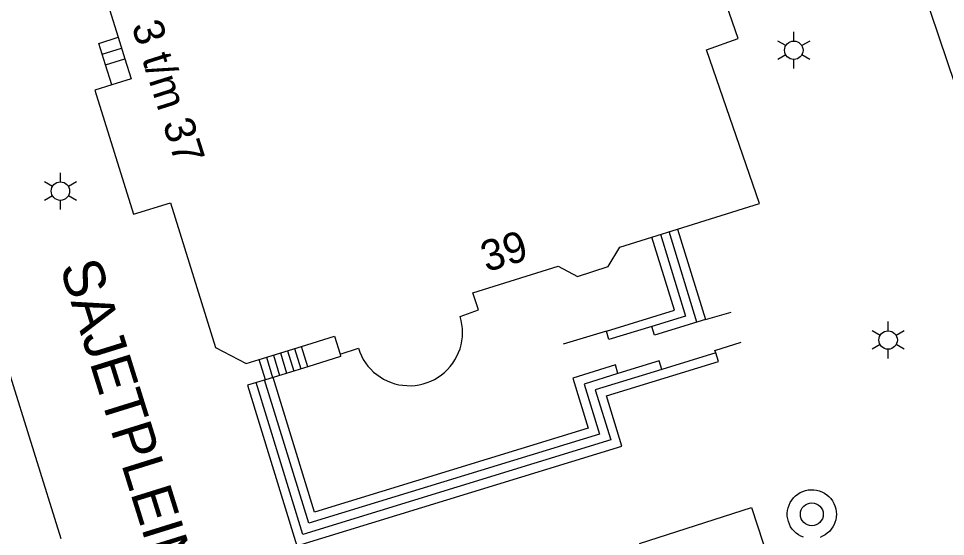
# Model space of a CAD drawing. Extents: x 122462 to 123306, y 485548 to 486417.
# Drawn here: x 122737.17 to 122782.47, y 485976.7 to 486002.03 of the extents above; entities that cross this region are included whole.
import ezdxf

# ---------------------------------------------------------------- set-up
doc = ezdxf.new("R2010")
doc.units = 0
for name, color, linetype in [('B-WE-IE-MEUBILAIR_WEGMEUBILAIR_VERKEERSBORD-S', 7, 'Continuous'), ('Level 1', 7, 'Continuous'), ('Level 17', 7, 'Continuous'), ('Level 22', 7, 'Continuous'), ('Level 30', 7, 'Continuous'), ('Level 31', 7, 'Continuous'), ('Level 33', 7, 'Continuous'), ('Level 50', 7, 'Continuous'), ('Level 53', 7, 'Continuous'), ('N-WE-GR-BOOM_DOORWORTELBARE RUIMTE-G', 7, 'Continuous')]:
    doc.layers.add(name, color=color, linetype=linetype)

msp = doc.modelspace()

# ---------------------------------------------------------------- linework, layer by layer
at = {"layer": 'Level 1'}
for p, q in [((122742.047, 486001.11), (122742.374, 486000.064)), ((122768.123, 485991.344), (122769.382, 485991.735)), ((122748.937, 485985.362), (122751.002, 485985.998))]:
    msp.add_line(p, q, dxfattribs=at)
for points in [[(122769.382, 485991.735), (122773.379, 485992.979), (122770.801, 486000.495), (122772.347, 486001.049), (122768.48, 486012.214), (122766.934, 486011.66), (122765.489, 486015.809), (122762.16, 486015.37), (122762.111, 486015.511), (122758.815, 486014.935)], [(122787.249, 485986.219), (122784.617, 485994.164), (122784.519, 485994.13), (122781.37, 486003.489), (122781.464, 486003.523), (122780.204, 486007.34), (122779.88, 486007.229), (122778.84, 486010.312)], [(122741.239, 486007.623), (122740.478, 486006.134), (122742.047, 486001.11)], [(122742.374, 486000.064), (122742.678, 485999.087), (122741.727, 485998.784)], [(122741.727, 485998.784), (122740.902, 485998.519), (122742.798, 485992.458), (122744.591, 485993.01), (122746.797, 485985.94), (122748.292, 485985.163), (122748.937, 485985.362)], [(122752.882, 485985.619), (122753.781, 485985.909), (122753.847, 485985.721), (122753.928, 485985.538), (122754.022, 485985.362), (122754.13, 485985.194), (122754.25, 485985.034), (122754.382, 485984.884), (122754.525, 485984.745), (122754.678, 485984.617), (122754.84, 485984.501), (122755.011, 485984.398), (122755.19, 485984.309), (122755.375, 485984.233), (122755.565, 485984.172), (122755.759, 485984.125), (122755.956, 485984.094), (122756.155, 485984.077), (122756.355, 485984.076), (122756.554, 485984.091), (122756.751, 485984.12), (122756.946, 485984.165), (122757.137, 485984.224), (122757.322, 485984.298), (122757.501, 485984.385), (122757.674, 485984.487), (122757.837, 485984.601), (122757.992, 485984.727), (122758.136, 485984.865), (122758.27, 485985.013), (122758.392, 485985.172), (122758.501, 485985.339), (122758.597, 485985.514), (122758.679, 485985.696), (122758.747, 485985.883), (122758.801, 485986.076), (122758.84, 485986.271), (122758.863, 485986.47), (122758.872, 485986.669), (122758.865, 485986.869), (122758.843, 485987.067), (122758.805, 485987.263), (122758.753, 485987.456), (122759.656, 485987.782), (122759.373, 485988.621), (122763.536, 485989.916), (122764.489, 485989.41), (122765.991, 485989.903), (122766.559, 485990.857), (122768.123, 485991.344)], [(122733.475, 485990.149), (122733.73, 485990.221), (122733.739, 485990.192), (122734.831, 485990.479), (122735.166, 485989.288), (122735.272, 485989.314), (122739.244, 485976.609)], [(122751.002, 485985.998), (122752.614, 485986.495), (122752.882, 485985.619)]]:
    msp.add_lwpolyline(points, dxfattribs=at)
at = {"layer": 'Level 17'}
msp.add_lwpolyline([(122775.529, 485976.661), (122775.402, 485976.716), (122775.283, 485976.785), (122775.172, 485976.866), (122775.072, 485976.96), (122774.982, 485977.065), (122774.906, 485977.18), (122774.843, 485977.302), (122774.794, 485977.431), (122774.761, 485977.565), (122774.743, 485977.701), (122774.74, 485977.839), (122774.754, 485977.976), (122774.783, 485978.111), (122774.828, 485978.241), (122774.887, 485978.366), (122774.96, 485978.482), (122775.046, 485978.59), (122775.143, 485978.687), (122775.252, 485978.773), (122775.369, 485978.845), (122775.494, 485978.903), (122775.624, 485978.947), (122775.759, 485978.976), (122775.896, 485978.989), (122776.034, 485978.986), (122776.17, 485978.967), (122776.304, 485978.933), (122776.432, 485978.884), (122776.555, 485978.82), (122776.669, 485978.743), (122776.773, 485978.653), (122776.867, 485978.552), (122776.948, 485978.44), (122777.016, 485978.321), (122777.07, 485978.194), (122777.108, 485978.062), (122777.132, 485977.926), (122777.14, 485977.788), (122777.132, 485977.651), (122777.108, 485977.515), (122777.069, 485977.383), (122777.032, 485977.292), (122776.968, 485977.17), (122776.89, 485977.056), (122776.8, 485976.952), (122776.698, 485976.859), (122776.587, 485976.778), (122776.467, 485976.711), (122776.34, 485976.658)], dxfattribs=at)
at = {"layer": 'Level 22'}
msp.add_lwpolyline([(122767.513, 485976.36), (122772.987, 485978.112), (122773.834, 485975.529)], dxfattribs=at)
at = {"layer": 'Level 30'}
for p, q in [((122741.42, 485999.766), (122742.374, 486000.064)), ((122741.727, 485998.784), (122741.42, 485999.766)), ((122751.308, 485985.002), (122751.002, 485985.998))]:
    msp.add_line(p, q, dxfattribs=at)
msp.add_lwpolyline([(122752.882, 485985.619), (122752.913, 485985.496), (122751.308, 485985.002)], dxfattribs=at)
at = {"layer": 'Level 31'}
for p, q in [((122749.242, 485984.368), (122748.937, 485985.362)), ((122751.308, 485985.002), (122749.619, 485984.484)), ((122749.619, 485984.484), (122749.242, 485984.368))]:
    msp.add_line(p, q, dxfattribs=at)
for points in [[(122741.42, 485999.766), (122741.093, 486000.812), (122742.047, 486001.11)], [(122769.382, 485991.735), (122770.741, 485987.313), (122768.256, 485986.551), (122768.127, 485986.972), (122766.027, 485986.327), (122765.898, 485986.747), (122769.221, 485987.768), (122768.123, 485991.344)], [(122749.242, 485984.368), (122748.357, 485984.095), (122750.77, 485976.243), (122766.661, 485981.126), (122765.908, 485983.575), (122771.373, 485985.255), (122771.244, 485985.676), (122768.61, 485984.866), (122768.48, 485985.287), (122766.467, 485984.668), (122766.338, 485985.088), (122764.259, 485984.449), (122765.011, 485982.004), (122751.643, 485977.896), (122749.619, 485984.484)]]:
    msp.add_lwpolyline(points, dxfattribs=at)
at = {"layer": 'Level 33'}
for p, q in [((122741.256, 486000.289), (122742.21, 486000.587)), ((122770.322, 485987.185), (122768.961, 485991.614)), ((122770.741, 485987.313), (122772, 485987.67)), ((122765.898, 485986.747), (122763.79, 485986.1)), ((122750.658, 485985.892), (122750.963, 485984.897)), ((122749.282, 485985.468), (122749.587, 485984.474)), ((122749.626, 485985.574), (122749.931, 485984.58)), ((122749.97, 485985.68), (122750.275, 485984.685)), ((122750.314, 485985.786), (122750.619, 485984.791))]:
    msp.add_line(p, q, dxfattribs=at)
for points in [[(122768.541, 485991.484), (122769.771, 485987.477), (122768.127, 485986.972)], [(122771.244, 485985.676), (122771.205, 485985.803), (122772.489, 485986.198)], [(122768.61, 485984.866), (122765.36, 485983.867), (122766.112, 485981.422), (122751.061, 485976.797), (122748.778, 485984.225)], [(122766.467, 485984.668), (122764.809, 485984.158), (122765.561, 485981.713), (122751.352, 485977.347), (122749.199, 485984.355)]]:
    msp.add_lwpolyline(points, dxfattribs=at)
at = {"layer": 'Level 50'}
for p, q in [((122775.06, 486000.929), (122775.06, 486001.379)), ((122774.67, 486000.704), (122774.28, 486000.929)), ((122775.839, 486000.929), (122775.449, 486000.704)), ((122774.67, 486000.254), (122774.28, 486000.029)), ((122775.06, 485999.579), (122775.06, 486000.029)), ((122775.839, 486000.029), (122775.449, 486000.254)), ((122739.22, 485994.039), (122739.22, 485994.489)), ((122738.83, 485993.814), (122738.44, 485994.039)), ((122739.999, 485994.039), (122739.609, 485993.814)), ((122738.83, 485993.364), (122738.44, 485993.139)), ((122739.22, 485992.689), (122739.22, 485993.139)), ((122739.999, 485993.139), (122739.609, 485993.364)), ((122779.67, 485986.759), (122779.67, 485987.209)), ((122779.28, 485986.534), (122778.89, 485986.759)), ((122780.449, 485986.759), (122780.059, 485986.534)), ((122779.28, 485986.084), (122778.89, 485985.859)), ((122779.67, 485985.409), (122779.67, 485985.859)), ((122780.449, 485985.859), (122780.059, 485986.084))]:
    msp.add_line(p, q, dxfattribs=at)
for centre in [(122775.06, 486000.479), (122739.22, 485993.589), (122779.67, 485986.309)]:
    msp.add_circle(centre, 0.45, dxfattribs=at)
at = {"layer": 'Level 53'}
msp.add_circle((122775.94, 485977.79), 0.56, dxfattribs=at)

# ---------------------------------------------------------------- texts
at = {"layer": 'B-WE-IE-MEUBILAIR_WEGMEUBILAIR_VERKEERSBORD-S'}
for s, rotation, p in [('3 t/m 37', 287.6383, (122742.683, 486001.68)), ('39', 16.9325, (122760.037, 485989.621))]:
    msp.add_text(s, height=1.5, rotation=rotation, dxfattribs=at).set_placement(p)
at = {"layer": 'N-WE-GR-BOOM_DOORWORTELBARE RUIMTE-G'}
msp.add_text('SAJETPLEIN', height=2, rotation=287.3079, dxfattribs=at).set_placement((122739.176, 485989.899))

doc.saveas('drawing.dxf')
